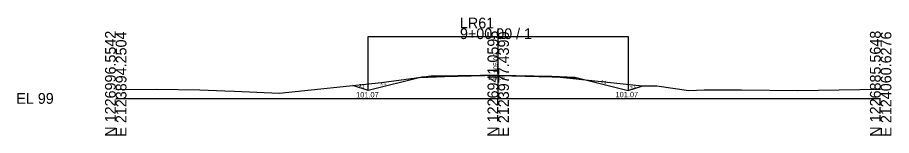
# Model space of a CAD drawing. Extents: x 2121193 to 2127979, y 1225108 to 1234639.
# Drawn here: x 2126750.9 to 2126979.4, y 1234107.5 to 1234138.4 of the extents above; entities that cross this region are included whole.
import ezdxf

# ---------------------------------------------------------------- set-up
doc = ezdxf.new("R2010")
doc.units = 0
for name, color, linetype in [('XS_CELL', 7, 'Continuous'), ('XS_M_DITCH', 7, 'Continuous'), ('XS_P_FINISHED_GRADE', 7, 'Continuous'), ('XS_P_FINISHED_GRADE_ELEV_TX', 7, 'Continuous'), ('XS_P_SUBGRADE_GRANULAR', 7, 'Continuous'), ('XS_P_SUBGRADE_PAVEMENT', 7, 'Continuous'), ('XS_P_TX_DCH', 7, 'Continuous'), ('XS_P_TX_FS_BS', 7, 'Continuous'), ('XS_X_GROUND', 7, 'Continuous'), ('XS_X_GROUND_TX', 7, 'Continuous')]:
    doc.layers.add(name, color=color, linetype=linetype)

msp = doc.modelspace()

# ---------------------------------------------------------------- linework, layer by layer
at = {"layer": 'XS_CELL'}
for p, q in [((2126876.61, 1234117.21), (2126876.61, 1234135.52)), ((2126776.61, 1234117.21), (2126876.61, 1234117.21)), ((2126876.61, 1234117.21), (2126976.61, 1234117.21))]:
    msp.add_line(p, q, dxfattribs=at)
at = {"layer": 'XS_M_DITCH'}
for p, q in [((2126842.61, 1234119.28), (2126842.61, 1234133.39)), ((2126842.61, 1234133.39), (2126910.61, 1234133.39)), ((2126910.61, 1234133.39), (2126910.61, 1234119.28))]:
    msp.add_line(p, q, dxfattribs=at)
at = {"layer": 'XS_P_FINISHED_GRADE'}
for p, q in [((2126856.61, 1234122.78), (2126842.61, 1234119.28)), ((2126862.61, 1234123.02), (2126856.61, 1234122.78)), ((2126876.61, 1234123.3), (2126862.61, 1234123.02)), ((2126876.61, 1234123.3), (2126890.61, 1234123.02)), ((2126890.61, 1234123.02), (2126896.61, 1234122.78)), ((2126896.61, 1234122.78), (2126910.61, 1234119.28)), ((2126842.61, 1234119.28), (2126838.62, 1234120.61)), ((2126910.61, 1234119.28), (2126914.39, 1234120.54))]:
    msp.add_line(p, q, dxfattribs=at)
at = {"layer": 'XS_P_SUBGRADE_GRANULAR'}
for p, q in [((2126862.54, 1234122.89), (2126856.02, 1234122.63)), ((2126890.68, 1234122.89), (2126897.2, 1234122.63))]:
    msp.add_line(p, q, dxfattribs=at)
at = {"layer": 'XS_P_SUBGRADE_PAVEMENT'}
for p, q in [((2126876.61, 1234123.17), (2126862.54, 1234122.89)), ((2126862.61, 1234123.02), (2126862.54, 1234122.89)), ((2126876.61, 1234123.17), (2126890.68, 1234122.89)), ((2126890.61, 1234123.02), (2126890.68, 1234122.89))]:
    msp.add_line(p, q, dxfattribs=at)
at = {"layer": 'XS_X_GROUND'}
for p, q in [((2126846.06, 1234121.41), (2126859.71, 1234123.21)), ((2126859.71, 1234123.21), (2126861.73, 1234123.11)), ((2126861.73, 1234123.11), (2126866.03, 1234123.17)), ((2126866.03, 1234123.17), (2126876.05, 1234123.31)), ((2126876.05, 1234123.31), (2126876.61, 1234123.3)), ((2126876.61, 1234123.3), (2126883.92, 1234123.15)), ((2126883.92, 1234123.15), (2126890.34, 1234123.01)), ((2126890.34, 1234123.01), (2126914.27, 1234120.54)), ((2126776.61, 1234119.54), (2126787.36, 1234119.66)), ((2126787.36, 1234119.66), (2126798.62, 1234119.46)), ((2126819.38, 1234118.55), (2126846.06, 1234121.41)), ((2126914.27, 1234120.54), (2126918.1, 1234120.53)), ((2126918.1, 1234120.53), (2126926.43, 1234119.27)), ((2126926.43, 1234119.27), (2126930.49, 1234119.48)), ((2126930.49, 1234119.48), (2126940.23, 1234119.49)), ((2126940.23, 1234119.49), (2126954.96, 1234119.32)), ((2126954.96, 1234119.32), (2126976.61, 1234119.61)), ((2126798.62, 1234119.46), (2126805.12, 1234119.19)), ((2126805.12, 1234119.19), (2126807.64, 1234119.13)), ((2126807.64, 1234119.13), (2126819.38, 1234118.55))]:
    msp.add_line(p, q, dxfattribs=at)

# ---------------------------------------------------------------- texts
at = {"layer": 'XS_CELL'}
for s, p in [('LR61', (2126866.61, 1234135.52)), ('9+00.00 / 1', (2126866.61, 1234132.72)), ('EL 99', (2126750.61, 1234115.81))]:
    msp.add_text(s, height=2.8, dxfattribs=at).set_placement(p)
for s, p in [('N 1226996.5542', (2126776.61, 1234107.21)), ('E 2123894.2504', (2126779.41, 1234107.21)), ('N 1226941.0595', (2126876.61, 1234107.21)), ('E 2123977.4390', (2126879.41, 1234107.21)), ('N 1226885.5648', (2126976.61, 1234107.21)), ('E 2124060.6276', (2126979.41, 1234107.21))]:
    msp.add_text(s, height=2.8, rotation=90, dxfattribs=at).set_placement(p)
at = {"layer": 'XS_P_FINISHED_GRADE_ELEV_TX'}
msp.add_text(' 105.09', height=1.25, rotation=90, dxfattribs=at).set_placement((2126876.61, 1234123.3))
at = {"layer": 'XS_P_TX_DCH'}
for p in [(2126839.45, 1234117.46), (2126907.29, 1234117.52)]:
    msp.add_text('101.07', height=1.4, dxfattribs=at).set_placement(p)
at = {"layer": 'XS_P_TX_FS_BS'}
for s, rotation, p in [('4:1', 345.9638, (2126903.38, 1234121.34)), ('3:1', 341.5651, (2126840.11, 1234120.31)), ('4:1', 14.0362, (2126845.89, 1234120.46)), ('3:1', 18.4349, (2126911.21, 1234119.62))]:
    msp.add_text(s, height=0.8, rotation=rotation, dxfattribs=at).set_placement(p)
at = {"layer": 'XS_X_GROUND_TX'}
msp.add_text('105.09', height=1, dxfattribs=at).set_placement((2126874.05, 1234122.14))

doc.saveas('drawing.dxf')
